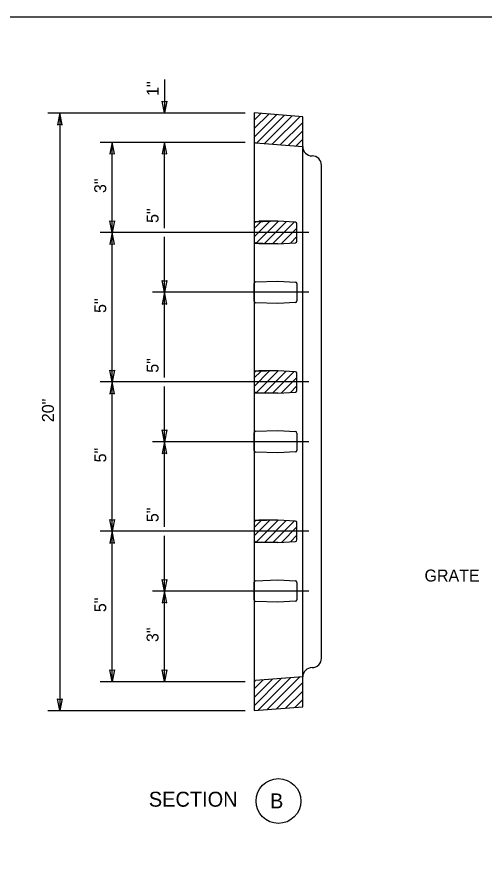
# Model space of a CAD drawing. Extents: x 99862 to 103151, y 100000 to 102076.
# Drawn here: x 101491 to 102117, y 100926 to 102076 of the extents above; entities that cross this region are included whole.
import ezdxf

# ---------------------------------------------------------------- set-up
doc = ezdxf.new("R2010")
doc.units = 0
for name, color, linetype in [('Level 1', 7, 'Continuous'), ('Level 15', 7, 'Continuous'), ('Level 17', 7, 'Continuous'), ('Level 2', 7, 'Continuous'), ('Level 20', 7, 'Continuous'), ('Level 9', 7, 'Continuous')]:
    doc.layers.add(name, color=color, linetype=linetype)

msp = doc.modelspace()

# ---------------------------------------------------------------- linework, layer by layer
at = {"layer": 'Level 1'}
for p, q in [((101808, 101909.2), (101808, 101185.3)), ((101898, 101217.3), (101898, 101877.3))]:
    msp.add_line(p, q, dxfattribs=at)
msp.add_lwpolyline([(99862, 99999.5), (103151, 99999.5), (103151, 102075.5), (99862, 102075.5)], close=True, dxfattribs=at)
for centre, start, end in [((101885.5, 101902.3), 180, 270), ((101885.5, 101877.3), 0, 90), ((101885.5, 101217.3), 270, 0), ((101885.5, 101192.3), 90, 180)]:
    msp.add_arc(centre, 12.5, start, end, dxfattribs=at)
at = {"layer": 'Level 15'}
for p, q in [((101688, 101992.1), (101688, 101947.3)), ((101532, 101947.3), (101796, 101947.3)), ((101548, 101947.3), (101548, 101147.3)), ((101602, 101908.2), (101796, 101908.2)), ((101618, 101787.3), (101618, 101908.2)), ((101688, 101793.3), (101688, 101908.2)), ((101881.3, 101787.3), (101602, 101787.3)), ((101618, 101587.3), (101618, 101787.3)), ((101688, 101707.3), (101688, 101781.3)), ((101881.3, 101707.3), (101672, 101707.3)), ((101688, 101593.3), (101688, 101707.3)), ((101881.3, 101587.3), (101602, 101587.3)), ((101618, 101387.3), (101618, 101587.3)), ((101688, 101507.3), (101688, 101581.3)), ((101881.3, 101507.3), (101672, 101507.3)), ((101688, 101393.3), (101688, 101507.3)), ((101881.3, 101387.3), (101602, 101387.3)), ((101618, 101186.3), (101618, 101387.3)), ((101688, 101307.3), (101688, 101381.3)), ((101881.3, 101307.3), (101672, 101307.3)), ((101688, 101186.3), (101688, 101307.3)), ((101602, 101186.3), (101796, 101186.3)), ((101532, 101147.3), (101796, 101147.3))]:
    msp.add_line(p, q, dxfattribs=at)
for points in [[(101688, 101947.3), (101684.9, 101963), (101688, 101962.3), (101691, 101963)], [(101548, 101947.3), (101544.9, 101931.5), (101548, 101932.3), (101551, 101931.5)], [(101618, 101908.2), (101614.9, 101892.5), (101618, 101893.2), (101621, 101892.5)], [(101688, 101908.2), (101684.9, 101892.5), (101688, 101893.2), (101691, 101892.5)], [(101618, 101787.3), (101614.9, 101803), (101618, 101802.3), (101621, 101803)], [(101618, 101787.3), (101614.9, 101771.5), (101618, 101772.3), (101621, 101771.5)], [(101688, 101707.3), (101684.9, 101723), (101688, 101722.3), (101691, 101723)], [(101688, 101707.3), (101684.9, 101691.5), (101688, 101692.3), (101691, 101691.5)], [(101618, 101587.3), (101614.9, 101603), (101618, 101602.3), (101621, 101603)], [(101618, 101587.3), (101614.9, 101571.5), (101618, 101572.3), (101621, 101571.5)], [(101688, 101507.3), (101684.9, 101523), (101688, 101522.3), (101691, 101523)], [(101688, 101507.3), (101684.9, 101491.5), (101688, 101492.3), (101691, 101491.5)], [(101618, 101387.3), (101614.9, 101403), (101618, 101402.3), (101621, 101403)], [(101618, 101387.3), (101614.9, 101371.5), (101618, 101372.3), (101621, 101371.5)], [(101688, 101307.3), (101684.9, 101323), (101688, 101322.3), (101691, 101323)], [(101688, 101307.3), (101684.9, 101291.5), (101688, 101292.3), (101691, 101291.5)], [(101618, 101186.3), (101614.9, 101202), (101618, 101201.3), (101621, 101202)], [(101688, 101186.3), (101684.9, 101202), (101688, 101201.3), (101691, 101202)], [(101548, 101147.3), (101544.9, 101163), (101548, 101162.3), (101551, 101163)]]:
    msp.add_lwpolyline(points, close=True, dxfattribs=at)
at = {"layer": 'Level 17'}
for p, q in [((101817, 101946.6), (101808, 101937.6)), ((101827.5, 101945.8), (101808, 101926.3)), ((101838, 101945), (101808, 101915)), ((101848.5, 101944.2), (101811.3, 101907)), ((101859, 101943.3), (101821.8, 101906.2)), ((101869.5, 101942.5), (101832.3, 101905.4)), ((101873, 101934.7), (101842.9, 101904.6)), ((101873, 101923.4), (101853.4, 101903.8)), ((101873, 101912.1), (101863.9, 101903)), ((101828.5, 101801.9), (101808, 101781.3)), ((101816.8, 101801.4), (101808, 101792.6)), ((101840.2, 101802.2), (101811.3, 101773.3)), ((101850.9, 101801.6), (101822.2, 101772.9)), ((101861.6, 101801), (101833.1, 101772.5)), ((101865.3, 101793.3), (101844.5, 101772.5)), ((101865.3, 101782), (101856.5, 101773.2)), ((101828.5, 101601.9), (101808, 101581.3)), ((101816.8, 101601.4), (101808, 101592.6)), ((101840.2, 101602.2), (101811.3, 101573.3)), ((101850.9, 101601.6), (101822.2, 101572.9)), ((101861.6, 101601), (101833.1, 101572.5)), ((101865.3, 101593.3), (101844.5, 101572.5)), ((101865.3, 101582), (101856.5, 101573.2)), ((101828.5, 101401.9), (101808, 101381.3)), ((101816.8, 101401.4), (101808, 101392.6)), ((101840.2, 101402.2), (101811.3, 101373.3)), ((101850.9, 101401.6), (101822.2, 101372.9)), ((101861.6, 101401), (101833.1, 101372.5)), ((101865.3, 101393.3), (101844.5, 101372.5)), ((101865.3, 101382), (101856.5, 101373.2)), ((101844.3, 101190.1), (101808, 101153.7)), ((101832.1, 101189.1), (101808, 101165)), ((101819.8, 101188.2), (101808, 101176.3)), ((101856.6, 101191), (101813.3, 101147.7)), ((101868.8, 101192), (101825.5, 101148.6)), ((101873, 101184.8), (101837.8, 101149.6)), ((101873, 101173.4), (101850, 101150.5)), ((101873, 101162.1), (101862.3, 101151.4))]:
    msp.add_line(p, q, dxfattribs=at)
at = {"layer": 'Level 2'}
for p, q in [((101873, 101192.3), (101873, 101902.3)), ((101839.7, 101802.3), (101814.1, 101802.3)), ((101839.7, 101772.3), (101814.1, 101772.3)), ((101839.7, 101602.3), (101814.1, 101602.3)), ((101839.7, 101572.3), (101814.1, 101572.3)), ((101839.7, 101402.3), (101814.1, 101402.3)), ((101839.7, 101372.3), (101814.1, 101372.3))]:
    msp.add_line(p, q, dxfattribs=at)
for points in [[(101809.9, 101907.1), (101873, 101902.3), (101873, 101942.3), (101808, 101947.3), (101808, 101909.2)], [(101808, 101799.1), (101808, 101775.4)], [(101863.3, 101800.9), (101839.7, 101802.3), (101810, 101801.2)], [(101865.3, 101775.7), (101865.3, 101798.9)], [(101810, 101773.3), (101839.7, 101772.3), (101863.3, 101773.6)], [(101808, 101695.4), (101808, 101719.1)], [(101810, 101721.2), (101839.7, 101722.3), (101863.3, 101720.9)], [(101865.3, 101718.9), (101865.3, 101695.7)], [(101863.3, 101693.6), (101839.7, 101692.3), (101810, 101693.3)], [(101863.3, 101600.9), (101839.7, 101602.3), (101810, 101601.2)], [(101808, 101599.1), (101808, 101575.4)], [(101865.3, 101575.7), (101865.3, 101598.9)], [(101810, 101573.3), (101839.7, 101572.3), (101863.3, 101573.6)], [(101810, 101521.2), (101839.7, 101522.3), (101863.3, 101520.9)], [(101808, 101495.4), (101808, 101519.1)], [(101865.3, 101518.9), (101865.3, 101495.7)], [(101863.3, 101493.6), (101839.7, 101492.3), (101810, 101493.3)], [(101808, 101399.1), (101808, 101375.4)], [(101863.3, 101400.9), (101839.7, 101402.3), (101810, 101401.2)], [(101865.3, 101375.7), (101865.3, 101398.9)], [(101810, 101373.3), (101839.7, 101372.3), (101863.3, 101373.6)], [(101808, 101295.4), (101808, 101319.1)], [(101810, 101321.2), (101839.7, 101322.3), (101863.3, 101320.9)], [(101865.3, 101318.9), (101865.3, 101295.7)], [(101863.3, 101293.6), (101839.7, 101292.3), (101810, 101293.3)], [(101808, 101185.3), (101808, 101147.3), (101873, 101152.3), (101873, 101192.3), (101809.9, 101187.4)]]:
    msp.add_lwpolyline(points, dxfattribs=at)
for centre, start, end in [((101810, 101909.2), 180, 265.6013), ((101810, 101799.1), 92.0522, 180), ((101863.2, 101798.9), 360, 86.758), ((101810, 101775.4), 180, 267.9478), ((101863.2, 101775.7), 273.242, 0), ((101810, 101719.1), 92.0522, 180), ((101863.2, 101718.9), 0, 86.758), ((101810, 101695.4), 180, 267.9478), ((101863.2, 101695.7), 273.242, 0), ((101810, 101599.1), 92.0522, 180), ((101863.2, 101598.9), 360, 86.758), ((101810, 101575.4), 180, 267.9478), ((101863.2, 101575.7), 273.242, 0), ((101810, 101519.1), 92.0522, 180), ((101863.2, 101518.9), 0, 86.758), ((101810, 101495.4), 180, 267.9478), ((101863.2, 101495.7), 273.242, 0), ((101810, 101399.1), 92.0522, 180), ((101863.2, 101398.9), 360, 86.758), ((101810, 101375.4), 180, 267.9478), ((101863.2, 101375.7), 273.242, 0), ((101810, 101319.1), 92.0522, 180), ((101863.2, 101318.9), 0, 86.758), ((101810, 101295.4), 180, 267.9478), ((101863.2, 101295.7), 273.242, 0), ((101810, 101185.3), 94.3987, 180)]:
    msp.add_arc(centre, 2.09, start, end, dxfattribs=at)
for centre, major_axis, start_param, end_param in [((101813, 101802.4), (5, 0.18), 3.139963, 4.946409), ((101813, 101772.1), (-5, 0.18), 4.478369, 6.284815), ((101813, 101602.4), (5, 0.18), 3.139963, 4.946409), ((101813, 101572.1), (-5, 0.18), 4.478369, 6.284815), ((101813, 101402.4), (5, 0.18), 3.139963, 4.946409), ((101813, 101372.1), (-5, 0.18), 4.478369, 6.284815)]:
    msp.add_ellipse(centre, major_axis=major_axis, ratio=0.045396, start_param=start_param, end_param=end_param, dxfattribs=at)
at = {"layer": 'Level 9'}
msp.add_circle((101840.5, 101026.3), 30, dxfattribs=at)

# ---------------------------------------------------------------- texts
at = {"layer": 'Level 20'}
for s, p in [('1"', (101680, 101970.1)), ('3"', (101610, 101840.1)), ('5"', (101680, 101800.1)), ('5"', (101610, 101679.6)), ('5"', (101680, 101599.6)), ('20"', (101540, 101533.4)), ('5"', (101610, 101479.6)), ('5"', (101680, 101399.6)), ('5"', (101610, 101279.1)), ('3"', (101680, 101239.1))]:
    msp.add_text(s, height=16, rotation=90, dxfattribs=at).set_placement(p)
for s, height, p in [('GRATE', 16, (102036, 101320.1)), ('SECTION', 20, (101667, 101018.7)), ('B', 20, (101829.2, 101016.5))]:
    msp.add_text(s, height=height, dxfattribs=at).set_placement(p)

doc.saveas('drawing.dxf')
